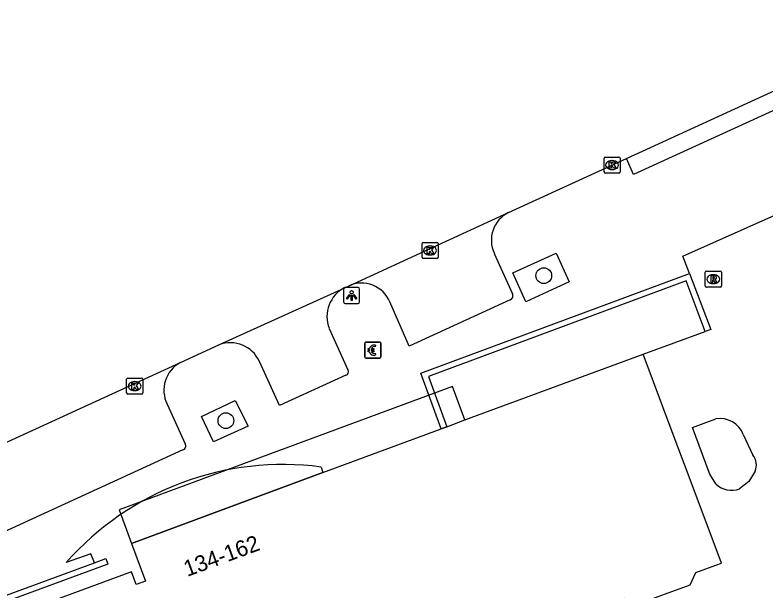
# Model space of a CAD drawing. Extents: x 160806 to 161707, y 383697 to 384148.
# Drawn here: x 160956.33 to 161003.06, y 383957.35 to 383993.17 of the extents above; entities that cross this region are included whole.
import ezdxf

# ---------------------------------------------------------------- set-up
doc = ezdxf.new("R2010")
doc.units = 0
for name, color, linetype in [('IMGEO_Betaalautomaat', 7, 'Continuous'), ('IMGEO_Boom', 7, 'Continuous'), ('IMGEO_Kolk', 7, 'Continuous'), ('IMGEO_Lichtpunt', 7, 'Continuous'), ('IMGEO_Muur', 7, 'Continuous'), ('IMGEO_Pand', 7, 'Continuous'), ('IMGEO_Pand_nummerreeks', 7, 'Continuous'), ('IMGEO_Pand_overbouw', 7, 'Continuous'), ('IMGEO_Rijbaan_lokaal_open', 7, 'Continuous'), ('IMGEO_Rioolput', 7, 'Continuous'), ('IMGEO_Voetpad_open', 7, 'Continuous')]:
    doc.layers.add(name, color=color, linetype=linetype)

msp = doc.modelspace()

# ---------------------------------------------------------------- linework, layer by layer
at = {"layer": 'IMGEO_Betaalautomaat'}
for p, q in [((160978.202, 383972.796), (160979.043, 383972.796)), ((160979.043, 383972.796), (160978.202, 383972.796)), ((160978.127, 383971.872), (160978.127, 383972.713)), ((160978.127, 383972.713), (160978.127, 383971.872)), ((160978.41, 383972.26), (160978.41, 383972.328)), ((160978.531, 383972.328), (160978.531, 383972.26)), ((160978.789, 383972.601), (160978.772, 383972.501)), ((160979.126, 383972.722), (160979.126, 383971.881)), ((160979.126, 383971.881), (160979.126, 383972.722)), ((160978.776, 383972.095), (160978.798, 383972.008)), ((160979.052, 383971.797), (160978.211, 383971.797)), ((160978.211, 383971.797), (160979.052, 383971.797))]:
    msp.add_line(p, q, dxfattribs=at)
for points in [[(160978.41, 383972.328), (160978.341, 383972.328), (160978.341, 383972.397), (160978.42, 383972.397)], [(160978.542, 383972.397), (160978.689, 383972.397), (160978.689, 383972.328), (160978.531, 383972.328)], [(160978.415, 383972.191), (160978.341, 383972.191), (160978.341, 383972.26), (160978.41, 383972.26)], [(160978.531, 383972.26), (160978.689, 383972.26), (160978.689, 383972.191), (160978.545, 383972.191)]]:
    msp.add_lwpolyline(points, dxfattribs=at)
for centre, radius, start, end in [((160978.205, 383972.719), 0.0779, 92.4484, 184.2845), ((160978.205, 383972.719), 0.0779, 92.4484, 184.2845), ((160979.049, 383972.719), 0.0779, 2.4484, 94.2845), ((160979.049, 383972.719), 0.0779, 2.4484, 94.2845), ((160978.703, 383972.321), 0.293, 73.014, 165.0139), ((160978.709, 383972.334), 0.179, 69.3236, 159.5683), ((160978.205, 383971.875), 0.0779, 182.4484, 274.2845), ((160978.205, 383971.875), 0.0779, 182.4484, 274.2845), ((160978.676, 383972.246), 0.267, 191.8096, 297.0389), ((160978.709, 383972.261), 0.179, 202.7625, 291.8693), ((160979.049, 383971.875), 0.0779, 272.4484, 4.2845), ((160979.049, 383971.875), 0.0779, 272.4484, 4.2845)]:
    msp.add_arc(centre, radius, start, end, dxfattribs=at)
at = {"layer": 'IMGEO_Boom'}
for centre in [(160989.277, 383976.933), (160969.47, 383967.898)]:
    msp.add_circle(centre, 0.489, dxfattribs=at)
at = {"layer": 'IMGEO_Kolk'}
for p, q in [((160993.03, 383983.397), (160993.03, 383984.249)), ((160993.105, 383984.323), (160993.957, 383984.323)), ((160993.518, 383984.103), (160993.543, 383984.103)), ((160994.031, 383984.249), (160994.031, 383983.397)), ((160993.541, 383983.543), (160993.516, 383983.543)), ((160993.957, 383983.323), (160993.105, 383983.323)), ((160981.689, 383978.076), (160981.689, 383978.928)), ((160981.764, 383979.002), (160982.616, 383979.002)), ((160982.69, 383978.928), (160982.69, 383978.076)), ((160982.177, 383978.782), (160982.202, 383978.782)), ((160982.616, 383978.002), (160981.764, 383978.002)), ((160982.2, 383978.222), (160982.175, 383978.222)), ((160963.287, 383969.623), (160963.287, 383970.475)), ((160963.362, 383970.549), (160964.214, 383970.549)), ((160964.288, 383970.475), (160964.288, 383969.623)), ((160963.775, 383970.329), (160963.8, 383970.329)), ((160964.214, 383969.549), (160963.362, 383969.549)), ((160963.798, 383969.769), (160963.773, 383969.769))]:
    msp.add_line(p, q, dxfattribs=at)
for points in [[(160993.03, 383983.397), (160993.03, 383984.249)], [(160993.105, 383984.323), (160993.957, 383984.323)], [(160993.351, 383984.023), (160993.474, 383984.023), (160993.474, 383983.872), (160993.604, 383984.023), (160993.768, 383984.023), (160993.622, 383983.872), (160993.775, 383983.623), (160993.623, 383983.623), (160993.538, 383983.787), (160993.474, 383983.72), (160993.474, 383983.623), (160993.351, 383983.623), (160993.351, 383984.023)], [(160994.031, 383984.249), (160994.031, 383983.397)], [(160993.957, 383983.323), (160993.105, 383983.323)], [(160981.689, 383978.076), (160981.689, 383978.928)], [(160981.764, 383979.002), (160982.616, 383979.002)], [(160982.69, 383978.928), (160982.69, 383978.076)], [(160982.01, 383978.702), (160982.133, 383978.702), (160982.133, 383978.551), (160982.263, 383978.702), (160982.427, 383978.702), (160982.281, 383978.551), (160982.434, 383978.302), (160982.282, 383978.302), (160982.197, 383978.466), (160982.133, 383978.399), (160982.133, 383978.302), (160982.01, 383978.302), (160982.01, 383978.702)], [(160982.616, 383978.002), (160981.764, 383978.002)], [(160963.287, 383969.623), (160963.287, 383970.475)], [(160963.362, 383970.549), (160964.214, 383970.549)], [(160964.288, 383970.475), (160964.288, 383969.623)], [(160963.608, 383970.249), (160963.731, 383970.249), (160963.731, 383970.098), (160963.861, 383970.249), (160964.025, 383970.249), (160963.879, 383970.098), (160964.032, 383969.849), (160963.88, 383969.849), (160963.795, 383970.013), (160963.731, 383969.946), (160963.731, 383969.849), (160963.608, 383969.849), (160963.608, 383970.249)], [(160964.214, 383969.549), (160963.362, 383969.549)]]:
    msp.add_lwpolyline(points, dxfattribs=at)
for centre, start, end in [((160993.107, 383984.247), 91.552, 178.448), ((160993.107, 383984.247), 91.552, 178.448), ((160993.955, 383984.247), 1.552, 88.448), ((160993.955, 383984.247), 1.552, 88.448), ((160993.107, 383983.399), 181.552, 268.448), ((160993.107, 383983.399), 181.552, 268.448), ((160993.955, 383983.399), 271.552, 358.448), ((160993.955, 383983.399), 271.552, 358.448), ((160981.766, 383978.926), 91.552, 178.448), ((160981.766, 383978.926), 91.552, 178.448), ((160982.614, 383978.926), 1.552, 88.448), ((160982.614, 383978.926), 1.552, 88.448), ((160981.766, 383978.078), 181.552, 268.448), ((160981.766, 383978.078), 181.552, 268.448), ((160982.614, 383978.078), 271.552, 358.448), ((160982.614, 383978.078), 271.552, 358.448), ((160963.364, 383970.473), 91.552, 178.448), ((160963.364, 383970.473), 91.552, 178.448), ((160964.212, 383970.473), 1.552, 88.448), ((160964.212, 383970.473), 1.552, 88.448), ((160963.364, 383969.625), 181.552, 268.448), ((160963.364, 383969.625), 181.552, 268.448), ((160964.212, 383969.625), 271.552, 358.448), ((160964.212, 383969.625), 271.552, 358.448)]:
    msp.add_arc(centre, 0.0765, start, end, dxfattribs=at)
for centre, major_axis, ratio, start_param, end_param in [((160993.517, 383983.823), (-0.387, 0.002), 0.722429, 4.712389, 7.853982), ((160993.542, 383983.823), (-0.39, 0.002), 0.717154, 1.570796, 4.712389), ((160982.176, 383978.502), (-0.387, 0.002), 0.722429, 4.712389, 7.853982), ((160982.201, 383978.502), (-0.39, 0.002), 0.717154, 1.570796, 4.712389), ((160963.774, 383970.049), (-0.387, 0.002), 0.722429, 4.712389, 7.853982), ((160963.799, 383970.049), (-0.39, 0.002), 0.717154, 1.570796, 4.712389)]:
    msp.add_ellipse(centre, major_axis=major_axis, ratio=ratio, start_param=start_param, end_param=end_param, dxfattribs=at)
at = {"layer": 'IMGEO_Lichtpunt'}
for p, q in [((160976.807, 383976.101), (160976.807, 383975.294)), ((160976.807, 383976.101), (160976.807, 383975.294)), ((160977.709, 383976.196), (160976.901, 383976.196)), ((160977.709, 383976.196), (160976.901, 383976.196)), ((160977.803, 383975.294), (160977.803, 383976.101)), ((160977.803, 383975.294), (160977.803, 383976.101)), ((160976.901, 383975.2), (160977.709, 383975.2)), ((160976.901, 383975.2), (160977.709, 383975.2))]:
    msp.add_line(p, q, dxfattribs=at)
for points in [[(160977.181, 383975.765), (160977.22, 383975.737), (160977.032, 383975.475), (160976.994, 383975.502), (160977.181, 383975.765)], [(160977.283, 383975.717), (160977.33, 383975.717), (160977.33, 383975.395), (160977.283, 383975.395), (160977.283, 383975.717)], [(160977.393, 383975.737), (160977.431, 383975.764), (160977.618, 383975.502), (160977.579, 383975.474), (160977.393, 383975.737)]]:
    msp.add_lwpolyline(points, dxfattribs=at)
msp.add_circle((160977.306, 383975.899), 0.0994, dxfattribs=at)
for centre, start, end in [((160976.901, 383976.101), 90, 180), ((160976.901, 383976.101), 90, 180), ((160977.709, 383976.101), 0, 90), ((160977.709, 383976.101), 0, 90), ((160976.901, 383975.294), 180, 270), ((160976.901, 383975.294), 180, 270), ((160977.709, 383975.294), 270, 0), ((160977.709, 383975.294), 270, 360)]:
    msp.add_arc(centre, 0.0946, start, end, dxfattribs=at)
at = {"layer": 'IMGEO_Muur'}
for points in [[(160982.89, 383967.398), (160981.624, 383970.857), (160998.353, 383977.077)], [(160998.353, 383977.077), (160999.676, 383973.574), (160999.337, 383973.451)], [(160999.337, 383973.451), (160998.143, 383976.615), (160982.085, 383970.645), (160983.228, 383967.523)], [(160961.285, 383959.048), (160961.982, 383959.305), (160962.106, 383958.967), (160948.954, 383954.127), (160951.945, 383946.07), (160951.608, 383945.945), (160948.491, 383954.34)], [(160948.491, 383954.34), (160961.285, 383959.048)]]:
    msp.add_lwpolyline(points, dxfattribs=at)
at = {"layer": 'IMGEO_Pand'}
for points in [[(160964.049, 383920.98), (160968.743, 383922.704), (160969.3, 383922.908), (160972.116, 383923.943), (160977.173, 383925.8), (160969.36, 383947.074), (160968.633, 383946.807), (160968.457, 383947.286), (160989.798, 383955.124), (160990.551, 383954.776), (160993.927, 383956.015), (160994.304, 383956.829), (160995.097, 383956.462), (160998.389, 383957.671), (160998.749, 383958.448), (161000, 383958.902), (161000.341, 383959.026), (160998.393, 383964.227), (160997.341, 383967.036), (160995.462, 383972.051)], [(160983.228, 383967.523), (160984.364, 383967.944), (160995.462, 383972.051)], [(161000, 383963.955), (160999.621, 383964.561), (160999.583, 383964.664), (160998.549, 383967.48), (161000, 383968.013)], [(160975.504, 383964.664), (160982.89, 383967.398)], [(160983.228, 383967.523), (160982.89, 383967.398)], [(161001.707, 383967.03), (161002.304, 383965.748)], [(160975.504, 383964.664), (160963.59, 383960.254), (160964.46, 383957.905), (160963.873, 383957.689), (160963.583, 383958.479), (160958.126, 383956.475), (160958.56, 383955.294), (160955.925, 383954.326), (160957.713, 383949.459), (160956.787, 383949.119), (160958.794, 383943.656), (160959.589, 383943.948), (160959.797, 383943.383), (160956.293, 383942.096), (160964.049, 383920.98)], [(161002.444, 383964.746), (161002.049, 383964.116), (161001.466, 383963.653)]]:
    msp.add_lwpolyline(points, dxfattribs=at)
for centre, radius, start, end in [((161000.254, 383966.481), 1.553, 20.6974, 99.4304), ((161001.512, 383965.127), 1.007, 337.7883, 38.1195), ((161000.972, 383964.965), 1.402, 226.0883, 290.6312)]:
    msp.add_arc(centre, radius, start, end, dxfattribs=at)
at = {"layer": 'IMGEO_Pand_overbouw'}
msp.add_lwpolyline([(160963.59, 383960.254), (160975.504, 383964.664), (160982.89, 383967.398), (160983.228, 383967.523), (160984.364, 383967.944), (160983.592, 383970.029), (160962.818, 383962.339)], close=True, dxfattribs=at)
at = {"layer": 'IMGEO_Rijbaan_lokaal_open'}
for points in [[(160994.436, 383984.241), (161013.947, 383993.174)], [(160987.081, 383980.87), (160994.436, 383984.241)], [(160977.145, 383976.309), (160987.081, 383980.87)], [(160969.039, 383972.624), (160976.884, 383976.185)], [(160976.884, 383976.185), (160977.145, 383976.309)], [(160966.644, 383971.527), (160969.039, 383972.624)], [(160948.108, 383963.03), (160966.644, 383971.527)]]:
    msp.add_lwpolyline(points, dxfattribs=at)
at = {"layer": 'IMGEO_Rioolput'}
for p, q in [((160999.337, 383976.289), (160999.337, 383977.141)), ((160999.412, 383977.215), (161000.264, 383977.215)), ((160999.825, 383976.995), (160999.85, 383976.995)), ((161000.338, 383977.141), (161000.338, 383976.289)), ((161000.264, 383976.215), (160999.412, 383976.215)), ((160999.848, 383976.435), (160999.823, 383976.435))]:
    msp.add_line(p, q, dxfattribs=at)
for points in [[(160999.337, 383976.289), (160999.337, 383977.141)], [(160999.412, 383977.215), (161000.264, 383977.215)], [(161000.338, 383977.141), (161000.338, 383976.289)], [(160999.926, 383976.913), (160999.674, 383976.915), (160999.674, 383976.515)], [(160999.674, 383976.515), (160999.798, 383976.515), (160999.798, 383976.677), (160999.809, 383976.677)], [(160999.852, 383976.834), (160999.798, 383976.834), (160999.798, 383976.753)], [(160999.798, 383976.753), (160999.85, 383976.753)], [(160999.856, 383976.648), (160999.927, 383976.515), (161000.067, 383976.515), (161000.002, 383976.641)], [(161000.264, 383976.215), (160999.412, 383976.215)]]:
    msp.add_lwpolyline(points, dxfattribs=at)
for centre, radius, start, end in [((160999.414, 383977.139), 0.0765, 91.552, 178.448), ((160999.414, 383977.139), 0.0765, 91.552, 178.448), ((161000.262, 383977.139), 0.0765, 1.552, 88.448), ((161000.262, 383977.139), 0.0765, 1.552, 88.448), ((160999.808, 383976.624), 0.0533, 26.0293, 88.6989), ((160999.834, 383976.942), 0.19, 274.7715, 282.9687), ((160999.858, 383976.738), 0.0964, 77.0061, 93.1865), ((160999.872, 383976.795), 0.0378, 276.6634, 79.6772), ((160999.925, 383976.803), 0.109, 350.3612, 89.416), ((160999.923, 383976.803), 0.112, 277.5842, 350.9817), ((160999.907, 383976.588), 0.108, 29.5134, 73.7905), ((160999.414, 383976.291), 0.0765, 181.552, 268.448), ((160999.414, 383976.291), 0.0765, 181.552, 268.448), ((161000.262, 383976.291), 0.0765, 271.552, 358.448), ((161000.262, 383976.291), 0.0765, 271.552, 358.448)]:
    msp.add_arc(centre, radius, start, end, dxfattribs=at)
for centre, major_axis, ratio, start_param, end_param in [((160999.824, 383976.715), (-0.387, 0.002), 0.722429, 4.712389, 7.853982), ((160999.849, 383976.715), (-0.39, 0.002), 0.717154, 1.570796, 4.712389)]:
    msp.add_ellipse(centre, major_axis=major_axis, ratio=ratio, start_param=start_param, end_param=end_param, dxfattribs=at)
at = {"layer": 'IMGEO_Voetpad_open'}
for points in [[(161013.947, 383993.174), (161014.397, 383992.177), (160994.873, 383983.238), (160994.436, 383984.241)], [(160998.353, 383977.077), (160997.944, 383978.148), (161004.053, 383980.875)], [(160986.194, 383978.318), (160987.326, 383975.794)], [(160990.864, 383976.556), (160988.161, 383975.312), (160987.346, 383977.115), (160990.056, 383978.339), (160990.864, 383976.556)], [(160987.176, 383975.419), (160980.898, 383972.536), (160979.689, 383975.299)], [(160975.907, 383973.651), (160977.076, 383971.073)], [(160995.462, 383972.051), (160999.337, 383973.451)], [(160976.947, 383970.727), (160972.804, 383968.835), (160971.556, 383971.592)], [(160970.848, 383967.553), (160968.702, 383966.582), (160967.951, 383968.157), (160970.057, 383969.155), (160970.848, 383967.553)], [(160965.817, 383968.924), (160966.933, 383966.462)], [(160966.786, 383966.074), (160952.025, 383959.31)], [(160975.411, 383965.01), (160975.504, 383964.664)], [(160961.285, 383959.048), (160961.058, 383959.607), (160959.525, 383959.063)]]:
    msp.add_lwpolyline(points, dxfattribs=at)
for centre, radius, start, end in [((160987.931, 383979.144), 1.923, 116.2195, 205.4486), ((160977.763, 383974.391), 1.998, 116.103, 201.7281), ((160977.914, 383974.536), 1.932, 23.2502, 113.4424), ((160987.092, 383975.67), 0.265, 288.468, 27.9292), ((160969.746, 383970.763), 1.991, 24.6138, 110.7977), ((160967.562, 383969.803), 1.954, 118.0231, 206.7257), ((160976.872, 383970.952), 0.237, 288.5193, 30.5865), ((160966.727, 383966.318), 0.251, 283.525, 34.975), ((160973.041, 383947.151), 18.016, 82.4394, 138.6078)]:
    msp.add_arc(centre, radius, start, end, dxfattribs=at)

# ---------------------------------------------------------------- texts
at = {"layer": 'IMGEO_Pand_nummerreeks'}
msp.add_text('134-162', height=1, rotation=20.2311, dxfattribs=at).set_placement((160967.061, 383958.162))

doc.saveas('drawing.dxf')
